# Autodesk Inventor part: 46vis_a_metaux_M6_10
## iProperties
Created: 2011-01
Part Number: 46vis_a_metaux_M6_10
Document SubType Name: Modeling
Designer: eric
Density: 1 g/cm^3
Mass: 0.629927 g
Surface Area: 5.79103 cm^2
Volume: 0.629927 cm^3
Author: eric
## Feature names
1. Base1
